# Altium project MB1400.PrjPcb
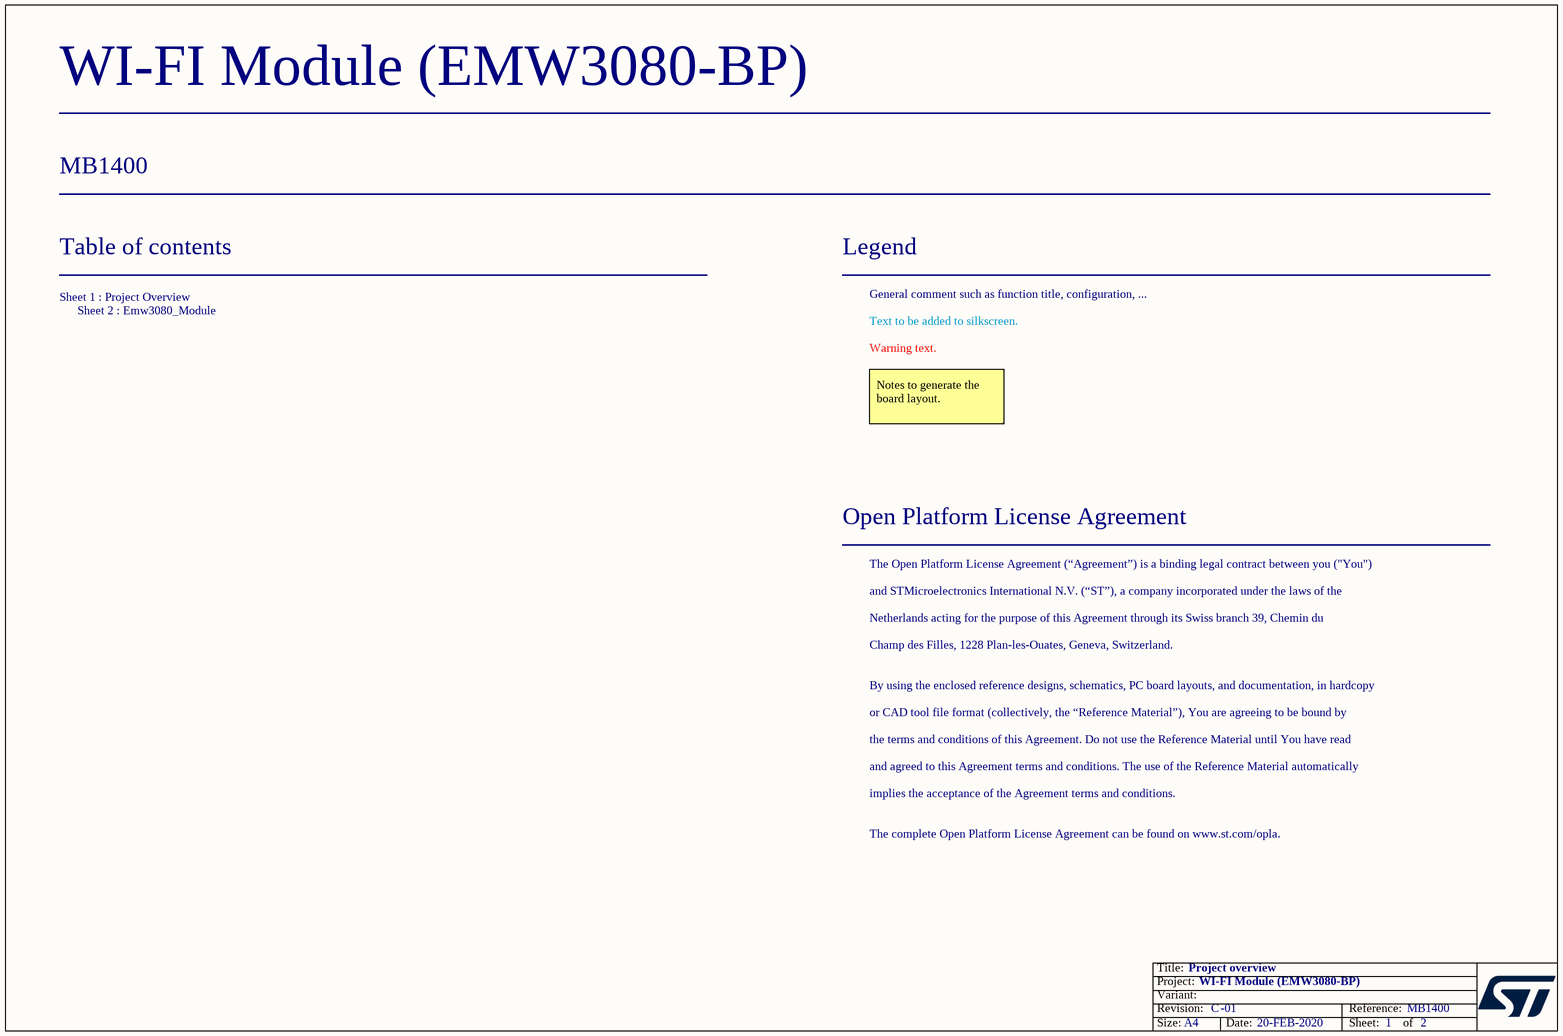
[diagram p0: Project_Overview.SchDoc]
Board_Assembly_Revision: 01; Board_Document_Date: 20-FEB-2020; Board_Name: WI-FI Module (EMW3080-BP); Board_PCB_Revision: C; Board_Reference: MB1400
2 sheets, 26 parts. Net scope: global (net labels, ports and power ports of the same name join across sheets).
Board file: MB1400.PcbDoc
Sheets:
  Project_Overview.SchDoc
  Emw3080_Module.SchDoc

## Sheet Project_Overview.SchDoc: Project overview
size A4; Date: Not used; ApprovedBy: Not used; CheckedBy: Not used; Author: Not used; CompanyName: STMicroelectronics; DrawnBy: Not used; Engineer: Not used; Organization: Not used; Address1: Not used; Address2: Not used; Address3: Not used; Address4: Not used; DocumentNumber: Not used; Revision: Not used; SheetNumber: 1; SheetTotal: 2

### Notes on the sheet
- Table of contents
- Legend
- General comment such as function title, configuration, ...
- Text to be added to silkscreen.
- Warning text.
- Notes to generate the board layout.
- Sheet 1 : Project Overview
  Sheet 2 : Emw3080_Module
- Open Platform License Agreement
- The Open Platform License Agreement (“Agreement”) is a binding legal contract between you ("You")
- and STMicroelectronics International N.V. (“ST”), a company incorporated under the laws of the
- Netherlands acting for the purpose of this Agreement through its Swiss branch 39, Chemin du
- Champ des Filles, 1228 Plan-les-Ouates, Geneva, Switzerland.
- By using the enclosed reference designs, schematics, PC board layouts, and documentation, in hardcopy
- or CAD tool file format (collectively, the “Reference Material”), You are agreeing to be bound by
- the terms and conditions of this Agreement. Do not use the Reference Material until You have read
- and agreed to this Agreement terms and conditions. The use of the Reference Material automatically
- implies the acceptance of the Agreement terms and conditions.
- The complete Open Platform License Agreement can be found on www.st.com/opla.

## Sheet Emw3080_Module.SchDoc: EMW3080_MODULE
size A3; Date: Not used; ApprovedBy: Not used; CheckedBy: Not used; Author: Not used; CompanyName: STMicroelectronics; DrawnBy: Not used; Engineer: Not used; Organization: Not used; Address1: Not used; Address2: Not used; Address3: Not used; Address4: Not used; DocumentNumber: Not used; Revision: Not used; SheetNumber: 2; SheetTotal: 2
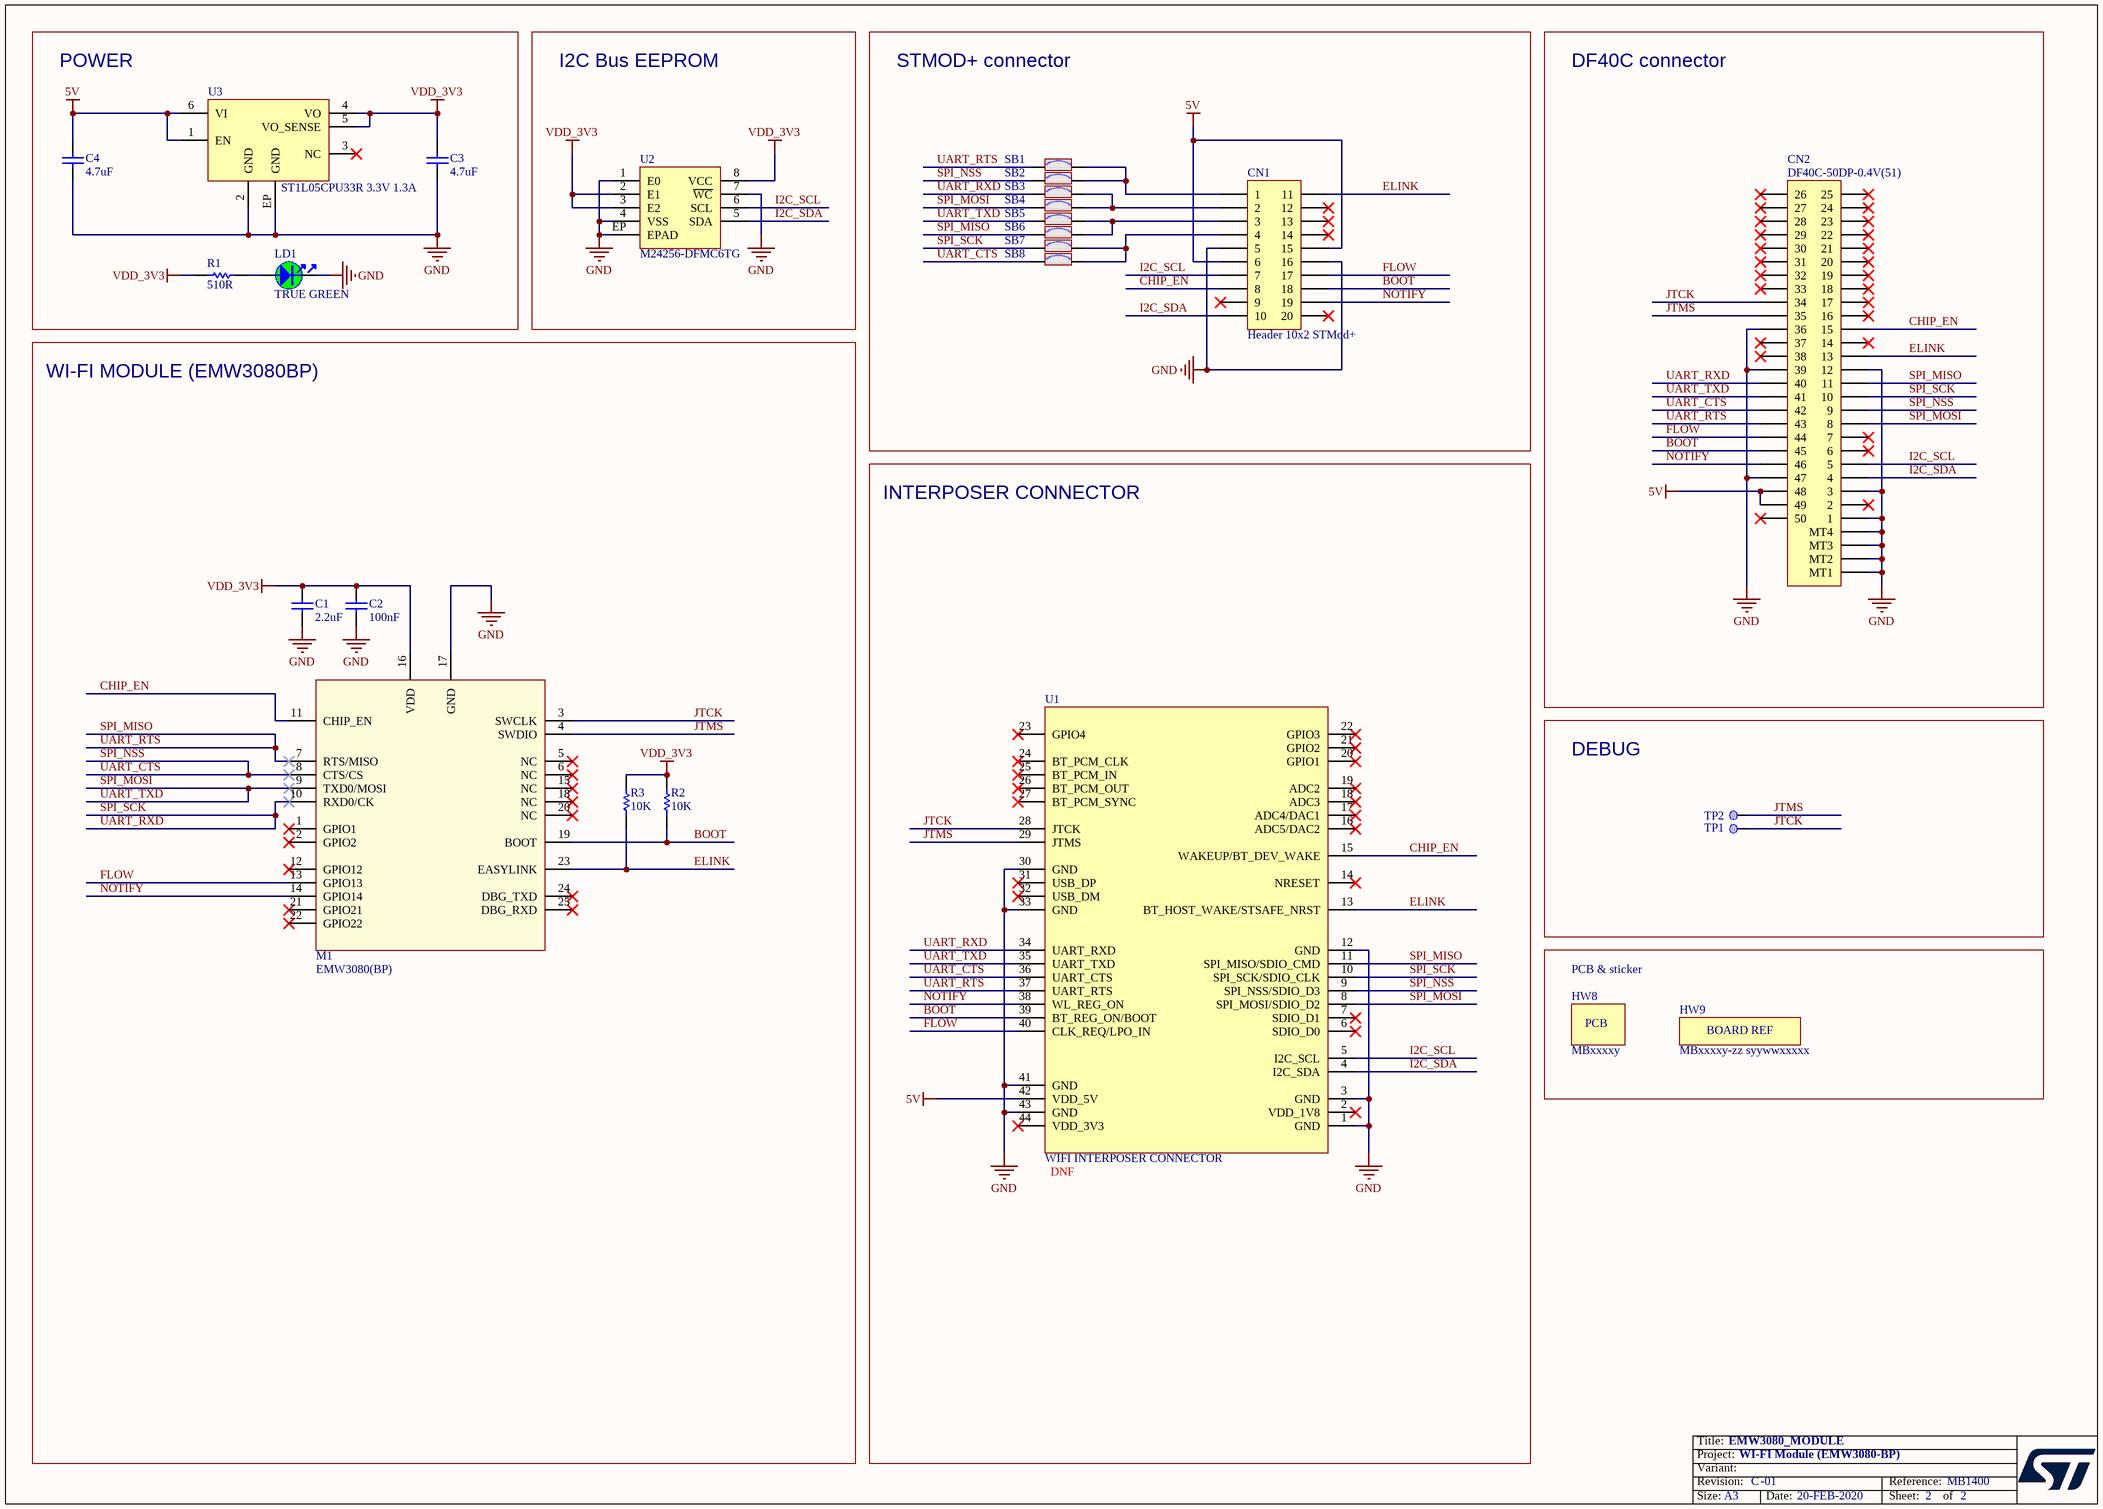
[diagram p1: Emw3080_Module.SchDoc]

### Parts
C1  value 2.2uF  [C0603]  (hidden comment: Capacitor)
C2  value 100nF  [C0402]  (hidden comment: Capacitor)
C3  value 4.7uF  [C0603]  (hidden comment: Capacitor)
C4  value 4.7uF  [C0603]  (hidden comment: Capacitor)
CN1  Header 10x2 STMod+  [CON_SAMTEC_TMM-110-01-L-D-RA__STMOD+]
CN2  DF40C-50DP-0.4V(51)  [CON_HRS_DF40C-50DP-0.4V_51]
HW8  value MBxxxxy  (hidden comment: PCB)  (no BOM)
HW9  value MBxxxxy-zz syywwxxxxx  [STICKER_25X9]  (hidden comment: STICKER_BOARD_REF)  (no BOM)
LD1  value TRUE GREEN  [LED_0603_VISHAY_VLMTG1300-GS08_GREEN_1A2K_H0P8]  (hidden comment: LED_green)
M1  EMW3080(BP)  [MOD_WIFI_MXCHIP_EMW3080-BP]
R1  value 510R  [R0402]  (hidden comment: Resistor)
R2  value 10K  [R0402]  (hidden comment: Resistor)
R3  value 10K  [R0402]  (hidden comment: Resistor)
SB1  SB_ON  [SOLDER-BRIDGE_R0402-0R]  (value not drawn)
SB2  SB_ON  [SOLDER-BRIDGE_R0402-0R]  (value not drawn)
SB3  SB_ON  [SOLDER-BRIDGE_R0402-0R]  (value not drawn)
SB4  SB_ON  [SOLDER-BRIDGE_R0402-0R]  (value not drawn)
SB5  SB_ON  [SOLDER-BRIDGE_R0402-0R]  (value not drawn)
SB6  SB_ON  [SOLDER-BRIDGE_R0402-0R]  (value not drawn)
SB7  SB_ON  [SOLDER-BRIDGE_R0402-0R]  (value not drawn)
SB8  SB_ON  [SOLDER-BRIDGE_R0402-0R]  (value not drawn)
TP1  Test Point  [TP_SMD_1MM]  (value not drawn)  (no BOM)
TP2  Test Point  [TP_SMD_1MM]  (value not drawn)  (no BOM)
U1  value WIFI INTERPOSER CONNECTOR  [CON_MOD2BOARD_WIFI_MURATA_LBEE5PA1LD]  (hidden comment: WIFI MODULE INTERPOSER)
U2  value M24256-DFMC6TG  [ICC_DFN8-EPAD_2X3_P050]  (hidden comment: M24128-DFMC6TP)
U3  value ST1L05CPU33R 3.3V 1.3A  [ICC_DFN6-EPAD_3X3_P095]  (hidden comment: ST1L05CPU33R)

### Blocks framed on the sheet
POWER: C3 C4 LD1 R1 U3
I2C Bus EEPROM: U2
STMOD+ connector: CN1 SB1-SB8
DF40C connector: CN2
WI-FI MODULE (EMW3080BP): C1 C2 M1 R2 R3
INTERPOSER CONNECTOR: U1
DEBUG: TP1 TP2
PCB & sticker: HW8 HW9

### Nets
5V: C4.2 CN1.6 CN1.15 CN2.48 CN2.49 U1.42(VDD_5V) U3.1(EN) U3.6(VI)
GND: C1.1 C2.1 C3.1 C4.1 CN1.5 CN1.16 CN2.1 CN2.3 CN2.12 CN2.36 CN2.39 CN2.47 CN2.MT1 CN2.MT2 CN2.MT3 CN2.MT4 LD1.2 M1.17(GND) U1.1(GND) U1.3(GND) U1.12(GND) U1.30(GND) U1.33(GND) U1.41(GND) U1.43(GND) U2.1(E0) U2.4(VSS) U2.7(~{WC}) U2.EP(EPAD) U3.2(GND) U3.EP(GND)
VDD_3V3: C1.2 C2.2 C3.2 M1.16(VDD) R1.1 R2.2 R3.2 U2.2(E1) U2.3(E2) U2.8(VCC) U3.4(VO) U3.5(VO_SENSE)
BOOT: CN1.18 CN2.45 M1.19(BOOT) R2.1 U1.39(BT_REG_ON/BOOT)
CHIP_EN: CN1.8 CN2.15 M1.11(CHIP_EN) U1.15(WAKEUP/BT_DEV_WAKE)
ELINK: CN1.11 CN2.13 M1.23(EASYLINK) R3.1 U1.13(BT_HOST_WAKE/STSAFE_NRST)
FLOW: CN1.17 CN2.44 M1.13(GPIO13) U1.40(CLK_REQ/LPO_IN)
I2C_SCL: CN1.7 CN2.5 U1.5(I2C_SCL) U2.6(SCL)
I2C_SDA: CN1.10 CN2.4 U1.4(I2C_SDA) U2.5(SDA)
JTCK: CN2.34 M1.3(SWCLK) TP1.1 U1.28(JTCK)
JTMS: CN2.35 M1.4(SWDIO) TP2.1 U1.29(JTMS)
NOTIFY: CN1.19 CN2.46 M1.14(GPIO14) U1.38(WL_REG_ON)
SPI_MISO: CN2.11 CN2.43 M1.7(RTS/MISO) SB1.1 SB6.1 U1.11(SPI_MISO/SDIO_CMD) U1.37(UART_RTS)  [also labelled UART_RTS]
SPI_MOSI: CN2.8 CN2.41 M1.9(TXD0/MOSI) SB4.1 SB5.1 U1.8(SPI_MOSI/SDIO_D2) U1.35(UART_TXD)  [also labelled UART_TXD]
SPI_NSS: CN2.9 CN2.42 M1.8(CTS/CS) SB2.1 SB8.1 U1.9(SPI_NSS/SDIO_D3) U1.36(UART_CTS)  [also labelled UART_CTS]
SPI_SCK: CN2.10 CN2.40 M1.10(RXD0/CK) SB3.1 SB7.1 U1.10(SPI_SCK/SDIO_CLK) U1.34(UART_RXD)  [also labelled UART_RXD]
NetCN1_1: CN1.1 SB1.2 SB2.2
NetCN1_2: CN1.2 SB3.2 SB4.2
NetCN1_3: CN1.3 SB5.2 SB6.2
NetCN1_4: CN1.4 SB7.2 SB8.2
NetLD1_1: LD1.1 R1.2

Not connected (* = marked no-connect by the designer): CN1 9* 12* 13* 14* 20*; CN2 2* 6* 7* 14* 16* 17* 18* 19* 20* 21* 22* 23* 24* 25* 26* 27* 28* 29* 30* 31* 32* 33* 37* 38* 50*; M1 1(GPIO1)* 2(GPIO2)* 5(NC)* 6(NC)* 12(GPIO12)* 15(NC)* 18(NC)* 20(NC)* 21(GPIO21)* 22(GPIO22)* 24(DBG_TXD)* 25(DBG_RXD)*; U1 2(VDD_1V8)* 6(SDIO_D0)* 7(SDIO_D1)* 14(NRESET)* 16(ADC5/DAC2)* 17(ADC4/DAC1)* 18(ADC3)* 19(ADC2)* 20(GPIO1)* 21(GPIO2)* 22(GPIO3)* 23(GPIO4)* 24(BT_PCM_CLK)* 25(BT_PCM_IN)* 26(BT_PCM_OUT)* 27(BT_PCM_SYNC)* 31(USB_DP)* 32(USB_DM)* 44(VDD_3V3)*; U3 3(NC)*

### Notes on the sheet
- (near U1) DNF

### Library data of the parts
C1 = MCD-00012: Capacitor, MLCC, 2.2uF, 10V, X5R, 10%, 0603, T=0,8mm; Manufacturer_Part_Number: CC0603KRX5R6BB225; Manufacturer: YAGEO; Alternate_Manufacturer_Part_Number: C0603C225K8PACTU; Alternate_Manufacturer: KEMET; Provided_By: SUBCO
C2 = MCD-00006: Capacitor, MLCC, 100nF, 16V, X7R, 10%, 0402, T=0.5mm; Manufacturer_Part_Number: CC0402KRX7R7BB104; Manufacturer: YAGEO; Alternate_Manufacturer_Part_Number: GCM155R71C104KA55D; Alternate_Manufacturer: MURATA; ECCN_US: EAR99; ECCN_EU: NEC; Provided_By: SUBCO
C3 C4 = MCD-00009: Capacitor, MLCC, 4.7uF, 16V, X5R, 10%, 0603, T=0.8mm; Manufacturer_Part_Number: CC0603KRX5R7BB475; Manufacturer: YAGEO; Provided_By: SUBCO
CN1 = MCD-00288: Header 10x2, 2mm, RA, TH, Height 3.20mm/3.50mm; Part_Type: Connector; Manufacturer_Part_Number: TMM-110-01-L-D-RA; Manufacturer: SAMTEC; Alternate_Manufacturer_Part_Number: PH200210C-07000; Alternate_Manufacturer: JIUBABA; Provided_By: SUBCO
CN2 = MCD-01227: Header 25x2, 0.4mm pitch, VR, SMT, Height 1.5mm; Part_Type: Connector; Manufacturer: HIROSE; Provided_By: SUBCO
HW8 = MCD-00216: PCB, xxxx for PCB number, Y for PCB revision; Part_Type: Mechanical; Provided_By: SUBCO
HW9 = MCD-00235: Sticker to mention board reference + serial number; Part_Type: Mechanical; Provided_By: SUBCO
LD1 = MCD-00589: LED Green, 0603 SMD, Fw Voltage = 2.8V - 3.6V; Part_Type: Display; Manufacturer_Part_Number: VLMTG1300-GS08; Manufacturer: VISHAY; Alternate_Manufacturer_Part_Number: LG Q396-PS-35; Alternate_Manufacturer: OSRAM OPTO SEMICONDUCTORS; Order_Code_RS: 7730452; Provided_By: Subcon; Initial_Board_Reference: MB1331
M1 = MCD-01500: Wi-Fi module 33x18mm, UART-SPI interface; Part_Type: IC; Manufacturer: MXCHIP; Provided_By: SUBCO
R1 = MCD-00064: Resistor,510R,0402,1%,1/16W; Manufacturer_Part_Number: RC0402FR-07510RL; Manufacturer: YAGEO; Provided_By: SUBCO
R2 R3 = MCD-00053: Resistor,10K,0402,1%,1/16W; Manufacturer_Part_Number: RC0402FR-0710KL; Manufacturer: YAGEO; BMS_Part_Number: 9131590; ECCN_US: EAR99; ECCN_EU: NEC; Provided_By: SUBCO
SB1-SB8 = MCD-01618: Solder Bridge 0402 ON; Part_Type: Mechanical; Manufacturer_Part_Number: RC0402JR-070RL; Manufacturer: YAGEO; Provided_By: SUBCO
TP1 TP2 = MCD-00074: Test Point 1mm; Part_Type: Mechanical
U1 = MCD-01334: 44 pins Generic Interposer Connector (Not Fitted : Footprint only)
U2 = MCD-01871: I2C Memory 3V3, 256Kbits, 2x3,0.55mm, UFDFPN8; Part_Type: IC; Manufacturer: STMICROELECTRONICS; Provided_By: SUBCO with ST control
U3 = MCD-01025: LDO, 3.3V, 1.3A, Very low quiescent current BiCMOS voltage regulator; Part_Type: IC; Manufacturer: STMICROELECTRONICS; BMS_Part_Number: 9176246; Provided_By: SUBCO with ST control

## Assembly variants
Soldered: not fitted CN1 CN2 SB1 SB2 SB3 SB4 SB5 SB6 SB7 SB8 U1
STMod+_SPI: not fitted CN2 SB1 SB3 SB5 SB8 U1
DFC40: not fitted CN1 SB1 SB2 SB3 SB4 SB5 SB6 SB7 SB8 U1
STMod+_UART: not fitted CN2 SB2 SB4 SB6 SB7 U1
